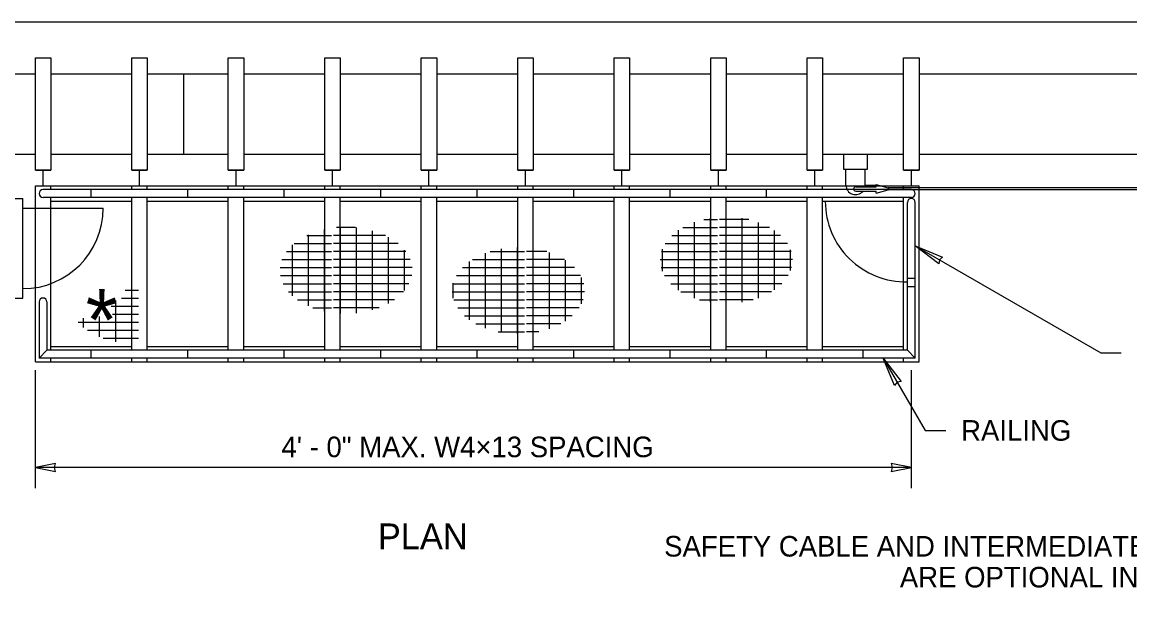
# Model space of a CAD drawing. Extents: x 99862 to 103151, y 100000 to 108076.
# Drawn here: x 100813 to 101674, y 101626 to 102076 of the extents above; entities that cross this region are included whole.
import ezdxf

# ---------------------------------------------------------------- set-up
doc = ezdxf.new("R2010")
doc.units = 0
for name, color, linetype in [('Level 1', 7, 'Continuous'), ('Level 11', 7, 'Continuous'), ('Level 15', 7, 'Continuous'), ('Level 2', 7, 'Continuous'), ('Level 20', 7, 'Continuous'), ('Level 23', 7, 'Continuous'), ('Level 26', 7, 'Continuous')]:
    doc.layers.add(name, color=color, linetype=linetype)

msp = doc.modelspace()

# ---------------------------------------------------------------- linework, layer by layer
at = {"layer": 'Level 1'}
msp.add_lwpolyline([(99862, 99999.5), (103151, 99999.5), (103151, 102075.5), (99862, 102075.5)], close=True, dxfattribs=at)
at = {"layer": 'Level 11'}
for p, q in [((101453.34, 101948.84), (101453.34, 101960.82)), ((101468.24, 101948.84), (101468.24, 101960.82)), ((101460.9, 101947.48), (101476.73, 101947.48)), ((101476.73, 101947.48), (101476.73, 101949.16)), ((101476.73, 101949.16), (101486.07, 101946.67)), ((101486.07, 101946.67), (101486.07, 101945.01)), ((102113.5, 101946.67), (101486.07, 101946.67)), ((101460.9, 101944.16), (101476.73, 101944.16)), ((101476.73, 101942.52), (101486.07, 101945.01)), ((101476.73, 101942.52), (101476.73, 101944.16)), ((102113.5, 101945.01), (101486.07, 101945.01))]:
    msp.add_line(p, q, dxfattribs=at)
for centre, radius, start, end in [((101460.79, 101948.84), 7.45, 180, 321.06769), ((101460.9, 101945.82), 1.66, 90, 270), ((101460.79, 101948.84), 7.45, 349.46919, 0)]:
    msp.add_arc(centre, radius, start, end, dxfattribs=at)
at = {"layer": 'Level 15'}
for p, q in [((101507.17, 101901.56), (101651.35, 101818.32)), ((101651.35, 101818.32), (101667.35, 101818.32)), ((101482.35, 101814.36), (101514.85, 101758.07)), ((100823.17, 101713.28), (100823.17, 101805)), ((101504.17, 101713.28), (101504.17, 101805)), ((101514.85, 101758.07), (101530.85, 101758.07)), ((101504.17, 101729.28), (100823.17, 101729.28))]:
    msp.add_line(p, q, dxfattribs=at)
for points in [[(101507.18, 101901.56), (101528.44, 101892.73), (101526.03, 101890.68), (101525.45, 101887.56)], [(101482.35, 101814.36), (101496.35, 101796.08), (101493.24, 101795.51), (101491.18, 101793.1)], [(100823.17, 101729.28), (100838.89, 101726.19), (100838.17, 101729.28), (100838.89, 101732.36)], [(101504.17, 101729.28), (101488.44, 101732.36), (101489.17, 101729.28), (101488.44, 101726.19)]]:
    msp.add_lwpolyline(points, close=True, dxfattribs=at)
at = {"layer": 'Level 2'}
for p, q in [((100785.17, 102035.32), (100823.17, 102035.32)), ((100835.17, 102035.32), (100898.17, 102035.32)), ((100910.17, 102035.32), (100973.17, 102035.32)), ((100938.54, 101972.82), (100938.54, 102035.32)), ((100985.17, 102035.32), (101048.17, 102035.32)), ((101060.17, 102035.32), (101123.17, 102035.32)), ((101122.67, 102035.32), (101123.17, 102035.32)), ((101135.17, 102035.32), (101198.17, 102035.32)), ((101210.17, 102035.32), (101273.17, 102035.32)), ((101285.17, 102035.32), (101348.17, 102035.32)), ((101360.17, 102035.32), (101423.17, 102035.32)), ((101435.17, 102035.32), (101498.17, 102035.32)), ((101510.17, 102035.32), (102305.1, 102035.32)), ((100785.17, 101972.82), (100823.17, 101972.82)), ((100835.17, 101972.82), (100898.17, 101972.82)), ((100910.17, 101972.82), (100973.17, 101972.82)), ((100985.17, 101972.82), (101048.17, 101972.82)), ((101060.17, 101972.82), (101123.17, 101972.82)), ((101122.67, 101972.82), (101123.17, 101972.82)), ((101135.17, 101972.82), (101198.17, 101972.82)), ((101210.17, 101972.82), (101273.17, 101972.82)), ((101285.17, 101972.82), (101348.17, 101972.82)), ((101360.17, 101972.82), (101423.17, 101972.82)), ((101435.17, 101972.82), (101498.17, 101972.82)), ((101510.17, 101972.82), (102305.1, 101972.82)), ((100823.17, 101960.32), (100835.17, 101960.32)), ((100829.17, 101948.32), (100829.17, 101960.32)), ((100898.17, 101960.32), (100910.17, 101960.32)), ((100904.17, 101948.32), (100904.17, 101960.32)), ((100973.17, 101960.32), (100985.17, 101960.32)), ((100979.17, 101948.32), (100979.17, 101960.32)), ((101048.17, 101960.32), (101060.17, 101960.32)), ((101054.17, 101948.32), (101054.17, 101960.32)), ((101123.17, 101960.32), (101135.17, 101960.32)), ((101129.17, 101948.32), (101129.17, 101960.32)), ((101198.17, 101960.32), (101210.17, 101960.32)), ((101204.17, 101948.32), (101204.17, 101960.32)), ((101273.17, 101960.32), (101285.17, 101960.32)), ((101279.17, 101948.32), (101279.17, 101960.32)), ((101348.17, 101960.32), (101360.17, 101960.32)), ((101354.17, 101948.32), (101354.17, 101960.32)), ((101423.17, 101960.32), (101435.17, 101960.32)), ((101429.17, 101948.32), (101429.17, 101960.32)), ((101498.17, 101960.32), (101510.17, 101960.32)), ((101504.17, 101948.32), (101504.17, 101960.32)), ((100823.17, 101948.32), (100835.17, 101948.32)), ((100823.17, 101811.32), (100823.17, 101948.32)), ((100823.17, 101948.32), (101510.17, 101948.32)), ((100835.17, 101945.28), (100835.17, 101948.32)), ((100898.17, 101948.32), (100910.17, 101948.32)), ((100898.17, 101945.28), (100898.17, 101948.32)), ((100910.17, 101945.28), (100910.17, 101948.32)), ((100973.17, 101948.32), (100985.17, 101948.32)), ((100973.17, 101945.28), (100973.17, 101948.32)), ((100985.17, 101945.28), (100985.17, 101948.32)), ((101048.17, 101948.32), (101060.17, 101948.32)), ((101048.17, 101945.28), (101048.17, 101948.32)), ((101060.17, 101945.28), (101060.17, 101948.32)), ((101123.17, 101948.32), (101135.17, 101948.32)), ((101123.17, 101945.28), (101123.17, 101948.32)), ((101135.17, 101945.28), (101135.17, 101948.32)), ((101198.17, 101948.32), (101210.17, 101948.32)), ((101198.17, 101945.28), (101198.17, 101948.32)), ((101210.17, 101945.28), (101210.17, 101948.32)), ((101273.17, 101948.32), (101285.17, 101948.32)), ((101273.17, 101945.28), (101273.17, 101948.32)), ((101285.17, 101945.28), (101285.17, 101948.32)), ((101348.17, 101948.32), (101360.17, 101948.32)), ((101348.17, 101945.28), (101348.17, 101948.32)), ((101360.17, 101945.28), (101360.17, 101948.32)), ((101423.17, 101948.32), (101435.17, 101948.32)), ((101423.17, 101945.28), (101423.17, 101948.32)), ((101435.17, 101945.28), (101435.17, 101948.32)), ((101468.24, 101948.82), (101476.73, 101948.82)), ((101498.17, 101945.28), (101498.17, 101948.32)), ((101498.17, 101948.32), (101510.17, 101948.32)), ((101510.17, 101811.32), (101510.17, 101948.32)), ((100569.17, 101938.32), (100813.44, 101938.32)), ((100813.44, 101860.82), (100813.44, 101938.32)), ((101504.21, 101945.28), (100829.14, 101945.28)), ((101504.21, 101939.28), (100829.14, 101939.28)), ((100835.17, 101820.36), (100835.17, 101939.28)), ((100866.67, 101939.28), (100866.67, 101945.28)), ((100898.17, 101820.36), (100898.17, 101939.28)), ((100910.17, 101820.36), (100910.17, 101939.28)), ((100941.67, 101939.28), (100941.67, 101945.28)), ((100973.17, 101820.36), (100973.17, 101939.28)), ((100985.17, 101820.36), (100985.17, 101939.28)), ((101016.67, 101939.28), (101016.67, 101945.28)), ((101048.17, 101820.36), (101048.17, 101939.28)), ((101060.17, 101820.36), (101060.17, 101939.28)), ((101091.67, 101939.28), (101091.67, 101945.28)), ((101123.17, 101820.36), (101123.17, 101939.28)), ((101135.17, 101820.36), (101135.17, 101939.28)), ((101166.67, 101939.28), (101166.67, 101945.28)), ((101198.17, 101820.36), (101198.17, 101939.28)), ((101210.17, 101820.36), (101210.17, 101939.28)), ((101241.67, 101939.28), (101241.67, 101945.28)), ((101273.17, 101820.36), (101273.17, 101939.28)), ((101285.17, 101820.36), (101285.17, 101939.28)), ((101316.67, 101939.28), (101316.67, 101945.28)), ((101348.17, 101820.36), (101348.17, 101939.28)), ((101360.17, 101820.36), (101360.17, 101939.28)), ((101391.67, 101939.28), (101391.67, 101945.28)), ((101423.17, 101820.36), (101423.17, 101939.28)), ((101435.17, 101820.36), (101435.17, 101939.28)), ((101498.17, 101820.36), (101498.17, 101939.28)), ((100813.44, 101930.82), (100875.94, 101930.82)), ((100835.17, 101936.32), (100898.17, 101936.32)), ((100910.17, 101936.32), (100973.17, 101936.32)), ((100985.17, 101936.32), (101048.17, 101936.32)), ((101060.17, 101936.32), (101123.17, 101936.32)), ((101135.17, 101936.32), (101198.17, 101936.32)), ((101210.17, 101936.32), (101273.17, 101936.32)), ((101285.17, 101936.32), (101348.17, 101936.32)), ((101360.17, 101936.32), (101423.17, 101936.32)), ((101435.17, 101936.32), (101498.17, 101936.32)), ((101501.17, 101820.36), (101501.17, 101935.38)), ((101507.17, 101814.36), (101507.17, 101935.38)), ((101501.17, 101876.35), (101507.17, 101876.35)), ((101501.17, 101870.08), (101507.17, 101870.08)), ((100569.17, 101860.82), (100813.44, 101860.82)), ((100826.16, 101858.03), (100826.16, 101814.36)), ((100832.16, 101858.03), (100832.16, 101820.36)), ((100832.16, 101820.36), (100826.16, 101814.36)), ((101501.17, 101820.36), (100832.16, 101820.36)), ((100835.17, 101823.32), (100898.17, 101823.32)), ((100866.67, 101814.36), (100866.67, 101820.36)), ((100910.17, 101823.32), (100973.17, 101823.32)), ((100941.67, 101814.36), (100941.67, 101820.36)), ((100985.17, 101823.32), (101048.17, 101823.32)), ((101016.67, 101814.36), (101016.67, 101820.36)), ((101060.17, 101823.32), (101123.17, 101823.32)), ((101091.67, 101814.36), (101091.67, 101820.36)), ((101135.17, 101823.32), (101198.17, 101823.32)), ((101166.67, 101814.36), (101166.67, 101820.36)), ((101210.17, 101823.32), (101273.17, 101823.32)), ((101241.67, 101814.36), (101241.67, 101820.36)), ((101285.17, 101823.32), (101348.17, 101823.32)), ((101316.67, 101814.36), (101316.67, 101820.36)), ((101360.17, 101823.32), (101423.17, 101823.32)), ((101391.67, 101814.36), (101391.67, 101820.36)), ((101435.17, 101823.32), (101498.17, 101823.32)), ((101466.67, 101814.36), (101466.67, 101820.36)), ((101507.17, 101814.36), (101501.17, 101820.36)), ((100823.17, 101811.32), (101510.17, 101811.32)), ((101507.17, 101814.36), (100826.16, 101814.36)), ((100835.17, 101811.32), (100835.17, 101814.36)), ((100898.17, 101811.32), (100898.17, 101814.36)), ((100910.17, 101811.32), (100910.17, 101814.36)), ((100973.17, 101811.32), (100973.17, 101814.36)), ((100985.17, 101811.32), (100985.17, 101814.36)), ((101048.17, 101811.32), (101048.17, 101814.36)), ((101060.17, 101811.32), (101060.17, 101814.36)), ((101123.17, 101811.32), (101123.17, 101814.36)), ((101135.17, 101811.32), (101135.17, 101814.36)), ((101198.17, 101811.32), (101198.17, 101814.36)), ((101210.17, 101811.32), (101210.17, 101814.36)), ((101273.17, 101811.32), (101273.17, 101814.36)), ((101285.17, 101811.32), (101285.17, 101814.36)), ((101348.17, 101811.32), (101348.17, 101814.36)), ((101360.17, 101811.32), (101360.17, 101814.36)), ((101423.17, 101811.32), (101423.17, 101814.36)), ((101435.17, 101811.32), (101435.17, 101814.36)), ((101498.17, 101811.32), (101498.17, 101814.36))]:
    msp.add_line(p, q, dxfattribs=at)
for points in [[(100823.17, 102047.82), (100835.17, 102047.82), (100835.17, 101960.32), (100823.17, 101960.32)], [(100898.17, 102047.82), (100910.17, 102047.82), (100910.17, 101960.32), (100898.17, 101960.32)], [(100973.17, 102047.82), (100985.17, 102047.82), (100985.17, 101960.32), (100973.17, 101960.32)], [(101048.17, 102047.82), (101060.17, 102047.82), (101060.17, 101960.32), (101048.17, 101960.32)], [(101123.17, 102047.82), (101135.17, 102047.82), (101135.17, 101960.32), (101123.17, 101960.32)], [(101198.17, 102047.82), (101210.17, 102047.82), (101210.17, 101960.32), (101198.17, 101960.32)], [(101273.17, 102047.82), (101285.17, 102047.82), (101285.17, 101960.32), (101273.17, 101960.32)], [(101348.17, 102047.82), (101360.17, 102047.82), (101360.17, 101960.32), (101348.17, 101960.32)], [(101423.17, 102047.82), (101435.17, 102047.82), (101435.17, 101960.32), (101423.17, 101960.32)], [(101498.17, 102047.82), (101510.17, 102047.82), (101510.17, 101960.32), (101498.17, 101960.32)]]:
    msp.add_lwpolyline(points, close=True, dxfattribs=at)
for centre, radius, start, end in [((100829.14, 101942.28), 3, 90, 270), ((101504.17, 101935.38), 3, 0, 180), ((101504.21, 101942.28), 3, 270, 90), ((100813.44, 101930.82), 62.5, 270, 0), ((101499.74, 101936.18), 62.5, 180, 271.31491), ((100829.16, 101858.03), 3, 0, 180)]:
    msp.add_arc(centre, radius, start, end, dxfattribs=at)
at = {"layer": 'Level 23'}
msp.add_lwpolyline([(101451.79, 101972.82), (101469.79, 101972.82), (101469.79, 101960.82), (101451.79, 101960.82)], close=True, dxfattribs=at)
at = {"layer": 'Level 26'}
for p, q in [((101342.88, 101922.09), (101353.39, 101922.09)), ((101348.06, 101857.76), (101348.06, 101923.11)), ((101377.7, 101922.09), (101354.95, 101922.09)), ((101360.27, 101856.8), (101360.27, 101924.07)), ((101372.77, 101857.8), (101372.77, 101923.07)), ((101048.06, 101850.73), (101048.06, 101914.38)), ((101072.1, 101915.85), (101057.33, 101915.85)), ((101060.27, 101849.05), (101060.27, 101916.07)), ((101072.77, 101849.34), (101072.77, 101915.78)), ((101085.26, 101851.72), (101085.26, 101913.39)), ((101323.07, 101867.22), (101323.07, 101913.65)), ((101326.6, 101915.85), (101353.39, 101915.85)), ((101335.57, 101860.94), (101335.57, 101919.93)), ((101393.99, 101915.85), (101354.95, 101915.85)), ((101385.26, 101861.03), (101385.26, 101919.84)), ((101397.76, 101867.4), (101397.76, 101913.48)), ((101034.15, 101909.61), (101053.39, 101909.61)), ((101035.57, 101854.85), (101035.57, 101910.27)), ((101095.29, 101909.61), (101054.95, 101909.61)), ((101097.76, 101856.78), (101097.76, 101908.33)), ((101318.03, 101909.61), (101353.39, 101909.61)), ((101402.55, 101909.61), (101354.95, 101909.61)), ((101018.36, 101897.13), (101053.39, 101897.13)), ((101023.07, 101862.82), (101023.07, 101902.3)), ((101024.31, 101903.37), (101053.39, 101903.37)), ((101105.12, 101903.37), (101054.95, 101903.37)), ((101111.07, 101897.13), (101054.95, 101897.13)), ((101110.25, 101866.93), (101110.25, 101898.19)), ((101173.07, 101837.58), (101173.07, 101895.88)), ((101176.7, 101897.13), (101203.39, 101897.13)), ((101185.57, 101834.21), (101185.57, 101899.25)), ((101198.06, 101833.1), (101198.06, 101900.36)), ((101220.74, 101897.13), (101204.95, 101897.13)), ((101210.27, 101833.95), (101210.27, 101899.51)), ((101222.77, 101837), (101222.77, 101896.46)), ((101309.89, 101897.13), (101353.39, 101897.13)), ((101310.58, 101881.82), (101310.58, 101899.05)), ((101312.82, 101903.37), (101353.39, 101903.37)), ((101407.77, 101903.37), (101354.95, 101903.37)), ((101410.69, 101897.13), (101354.95, 101897.13)), ((101410.25, 101882.47), (101410.25, 101898.4)), ((101014.89, 101890.89), (101053.39, 101890.89)), ((101114.61, 101890.89), (101054.95, 101890.89)), ((101160.58, 101844.17), (101160.58, 101889.29)), ((101162.94, 101890.89), (101203.39, 101890.89)), ((101234.51, 101890.89), (101204.95, 101890.89)), ((101235.26, 101843.06), (101235.26, 101890.4)), ((101308.87, 101890.89), (101353.39, 101890.89)), ((101411.71, 101890.89), (101354.95, 101890.89)), ((101013.39, 101884.65), (101053.39, 101884.65)), ((101013.68, 101878.41), (101053.39, 101878.41)), ((101116.04, 101884.65), (101054.95, 101884.65)), ((101115.75, 101878.41), (101054.95, 101878.41)), ((101150.49, 101878.41), (101203.39, 101878.41)), ((101155.2, 101884.65), (101203.39, 101884.65)), ((101242.25, 101884.65), (101204.95, 101884.65)), ((101246.95, 101878.41), (101204.95, 101878.41)), ((101309.63, 101884.65), (101353.39, 101884.65)), ((101312.27, 101878.41), (101353.39, 101878.41)), ((101410.95, 101884.65), (101354.95, 101884.65)), ((101408.32, 101878.41), (101354.95, 101878.41)), ((100898.13, 101827.06), (100898.13, 101877.35)), ((101015.81, 101872.17), (101053.39, 101872.17)), ((101113.63, 101872.17), (101054.95, 101872.17)), ((101147.97, 101872.17), (101203.39, 101872.17)), ((101148.08, 101860.86), (101148.08, 101872.6)), ((101249.47, 101872.17), (101204.95, 101872.17)), ((101247.76, 101856.59), (101247.76, 101876.87)), ((101317.11, 101872.17), (101353.39, 101872.17)), ((101403.47, 101872.17), (101354.95, 101872.17)), ((100890.22, 101860.9), (100903.39, 101860.9)), ((100892.88, 101867.14), (100903.39, 101867.14)), ((101020.02, 101865.93), (101053.39, 101865.93)), ((101109.42, 101865.93), (101054.95, 101865.93)), ((101147.31, 101865.93), (101203.39, 101865.93)), ((101250.13, 101865.93), (101204.95, 101865.93)), ((101325.07, 101865.93), (101353.39, 101865.93)), ((101395.51, 101865.93), (101354.95, 101865.93)), ((100882.23, 101854.66), (100903.39, 101854.66)), ((100885.63, 101827.06), (100885.63, 101858.97)), ((101027.01, 101859.69), (101053.39, 101859.69)), ((101038.96, 101853.45), (101053.39, 101853.45)), ((101102.42, 101859.69), (101054.95, 101859.69)), ((101090.47, 101853.45), (101054.95, 101853.45)), ((101148.44, 101859.69), (101203.39, 101859.69)), ((101151.48, 101853.45), (101203.39, 101853.45)), ((101249.01, 101859.69), (101204.95, 101859.69)), ((101245.97, 101853.45), (101204.95, 101853.45)), ((101339.45, 101859.69), (101353.39, 101859.69)), ((101381.13, 101859.69), (101354.95, 101859.69)), ((100860.64, 101838.21), (100860.64, 101845.39)), ((100873.14, 101830.76), (100873.14, 101846.72)), ((100883.03, 101848.42), (100903.39, 101848.42)), ((101156.85, 101847.21), (101203.39, 101847.21)), ((101240.6, 101847.21), (101204.95, 101847.21)), ((100856.58, 101842.18), (100903.39, 101842.18)), ((100863.61, 101835.94), (100903.39, 101835.94)), ((101165.66, 101840.97), (101203.39, 101840.97)), ((101182.9, 101834.73), (101203.39, 101834.73)), ((101231.78, 101840.97), (101204.95, 101840.97)), ((101214.55, 101834.73), (101204.95, 101834.73)), ((100875.85, 101829.7), (100903.39, 101829.7))]:
    msp.add_line(p, q, dxfattribs=at)

# ---------------------------------------------------------------- texts
at = {"layer": 'Level 20'}
for s, height, p in [('*', 48, (100862.31, 101820.04)), ('RAILING', 16, (101542.86, 101750.07)), ('4\' - 0" MAX. W4×13 SPACING', 16, (101014.49, 101737.28)), ('PLAN', 20, (101089.41, 101665.75)), ('SAFETY CABLE AND INTERMEDIATE SUPPORT', 16, (101311.99, 101660.02)), ('ARE OPTIONAL IN THIS ZONE', 16, (101495.24, 101636.02))]:
    msp.add_text(s, height=height, dxfattribs=at).set_placement(p)

doc.saveas('drawing.dxf')
